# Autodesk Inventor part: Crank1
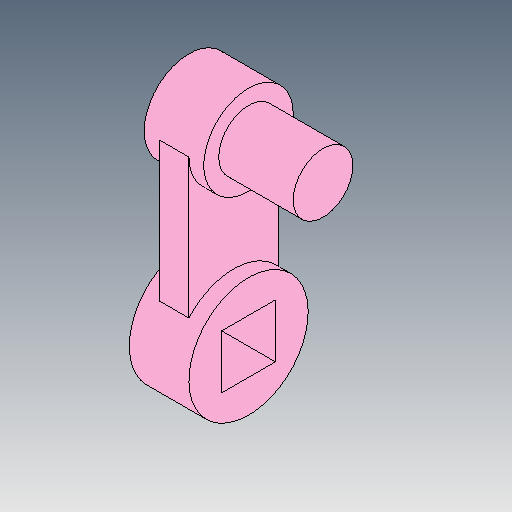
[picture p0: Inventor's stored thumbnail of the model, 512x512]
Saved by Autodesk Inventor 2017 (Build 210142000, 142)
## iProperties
Created: 2015-03
Part Number: Crank1
Document SubType Name: Modeling
Designer: Administrator
Density: 1 g/cm^3
Mass: 0.397864 g
Surface Area: 5.05232 cm^2
Volume: 0.397864 cm^3
Material: Generic
Appearance: Bubblegum
Author: Administrator
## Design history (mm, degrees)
sketch "Sketch6"
  geometry: L1 (1.8, -1.8)-(-1.8, -1.8); L2 (-1.8, -1.8)-(-1.8, 1.8); L3 (-1.8, 1.8)-(1.8, 1.8); L4 (1.8, 1.8)-(1.8, -1.8); L5 (0, 0)-(12, 0); L6 (12, 3)-(2.646, 3); L7 (12, -3)-(2.646, -3); A1 r 4 centre (0, 0) between (2.646, 3) and (2.646, -3); A2 r 3 centre (12, 0) between (12, -3) and (12, 3); 1 further point
  constraints: 14 end point, 4 point on circle, 3 coincident, 2 centre point, 2 parallel, 2 tangent, 1 horizontal, 9 other
  dimensions: "d27" = 3.6 distance between parallel lines of L2 L4; "d28" = 8 diameter of A1; "d29" = 12 distance of L5.start L5.end; "d30" = 6 diameter of A2
extrude "Extrusion5" new body sketch "Sketch6" stored distance "d31" = 4; taper "d32" = 0 deg
sketch "Sketch7"
  geometry: L1 (-3, 12)-(-3, 2.646) reference; L2 (3, 2.646)-(3, 12) reference; L3 (-3, 2.646)-(-3, 12); L4 (3, 2.646)-(3, 12); A1 r 4 centre (0, 0) between (-3, 2.646) and (3, 2.646) reference; A2 r 3 centre (0, 12) between (3, 12) and (-3, 12) reference; 3 further points
  constraints: 4 end point, 2 coincident, 2 collinear, 2 vertical, 1 horizontal alignment, 5 other
extrude "Extrusion6" cut sketch "Sketch7" distance "d33" = 1; taper "d34" = 0 deg
mirror "Mirror2"
sketch "Sketch8"
  geometry: C1 r 3 at (0, 0) reference; C2 r 2 at (0, 0); 1 further point
  constraints: 1 centre point
  dimensions: "d35" = 4 diameter of C2
extrude "Extrusion7" join sketch "Sketch8" distance "d36" = 5; taper "d37" = 0 deg
body "Solid2"
node "Projected Loop1"
